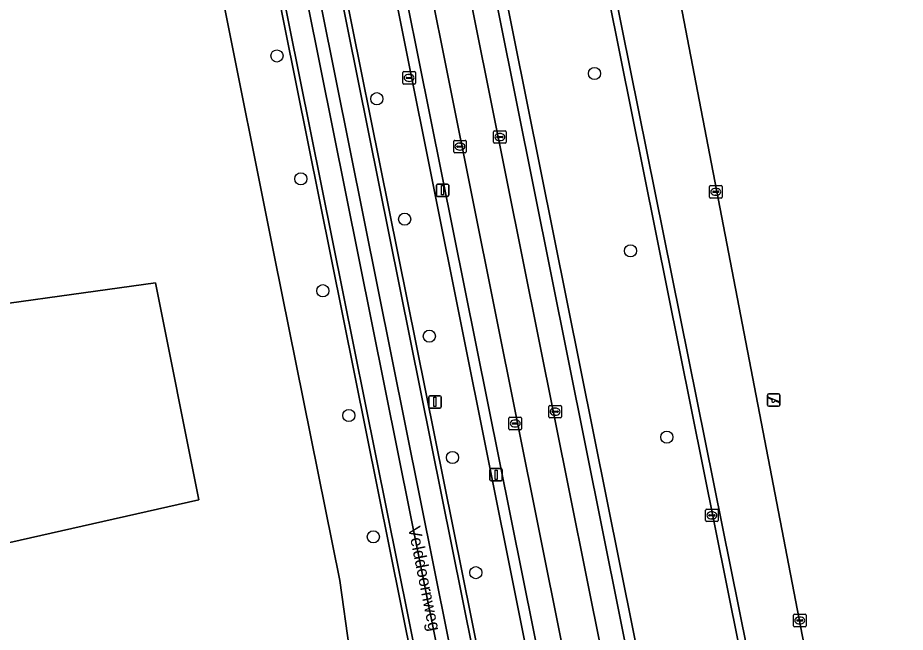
# Model space of a CAD drawing. Extents: x 160203 to 161530, y 379528 to 381797.
# Drawn here: x 160799.8 to 160871, y 380367.4 to 380416.8 of the extents above; entities that cross this region are included whole.
import ezdxf

# ---------------------------------------------------------------- set-up
doc = ezdxf.new("R2010")
doc.units = 0
for name, color, linetype in [('IMGEO_Berm_groen', 7, 'Continuous'), ('IMGEO_Berm_open', 7, 'Continuous'), ('IMGEO_Boom', 7, 'Continuous'), ('IMGEO_Erf', 7, 'Continuous'), ('IMGEO_Grasland_agrarisch', 7, 'Continuous'), ('IMGEO_Groenvoorziening', 7, 'Continuous'), ('IMGEO_Hek', 7, 'Continuous'), ('IMGEO_Kolk', 7, 'Continuous'), ('IMGEO_Lichtmast', 7, 'Continuous'), ('IMGEO_Loofbos', 7, 'Continuous'), ('IMGEO_Openbare_ruimte_label', 7, 'Continuous'), ('IMGEO_Parkeervlak_open', 7, 'Continuous'), ('IMGEO_Rijbaan_lokaal_gesloten', 7, 'Continuous'), ('IMGEO_Rijbaan_lokaal_open', 7, 'Continuous'), ('IMGEO_Rioolput', 7, 'Continuous'), ('IMGEO_Speelvoorziening', 7, 'Continuous'), ('IMGEO_Voetpad_open', 7, 'Continuous'), ('IMGEO_Waterleidingput', 7, 'Continuous')]:
    doc.layers.add(name, color=color, linetype=linetype)

msp = doc.modelspace()

# ---------------------------------------------------------------- linework, layer by layer
at = {"layer": 'IMGEO_Berm_groen'}
for points in [[(160830.916, 380414.289), (160819.918, 380469.339), (160814.915, 380494.379), (160811.026, 380493.513), (160814.089, 380478.303), (160841.379, 380342.789), (160841.726, 380341.019), (160841.352, 380340.899), (160841.381, 380340.684), (160841.823, 380340.142)], [(160845.412, 380338.924), (160846.061, 380339.046), (160841.959, 380359.232), (160830.916, 380414.289)]]:
    msp.add_lwpolyline(points, dxfattribs=at)
at = {"layer": 'IMGEO_Berm_open'}
msp.add_lwpolyline([(160809.488, 380490.62), (160808.357, 380496.254), (160807.806, 380496.157), (160807.391, 380496.064), (160808.139, 380492.044), (160808.457, 380490.462), (160846.915, 380299.112), (160856.862, 380248.916), (160857.878, 380249.092), (160847.878, 380299.47)], close=True, dxfattribs=at)
at = {"layer": 'IMGEO_Boom'}
for centre in [(160820.577, 380413.686), (160846.083, 380412.28), (160828.604, 380410.248), (160822.492, 380403.806), (160830.836, 380400.572), (160848.977, 380398.029), (160824.267, 380394.82), (160832.815, 380391.167), (160826.35, 380384.795), (160851.892, 380383.061), (160834.682, 380381.421), (160828.319, 380375.049), (160836.549, 380372.17)]:
    msp.add_circle(centre, 0.489, dxfattribs=at)
at = {"layer": 'IMGEO_Erf'}
for points in [[(160786.215, 380358.257), (160807.904, 380361.665), (160818.583, 380363.901), (160826.408, 380365.955), (160825.615, 380371.544), (160820.389, 380397.556), (160816.06, 380419.106), (160814.776, 380425.496), (160813.712, 380431.457), (160802.128, 380489.092), (160796.963, 380489.418)], [(160792.299, 380392.893), (160810.816, 380395.452), (160814.313, 380378.028), (160775.372, 380369.231)]]:
    msp.add_lwpolyline(points, dxfattribs=at)
at = {"layer": 'IMGEO_Grasland_agrarisch'}
msp.add_lwpolyline([(160770.881, 380415.989), (160759.176, 380415.089), (160754.769, 380413.373), (160762.756, 380386.034), (160764.96, 380380.474), (160767.455, 380377.256), (160770.696, 380373.902), (160775.372, 380369.231), (160814.313, 380378.028), (160810.816, 380395.452), (160792.299, 380392.893), (160790.929, 380411.368), (160771.323, 380410.232)], close=True, dxfattribs=at)
at = {"layer": 'IMGEO_Groenvoorziening'}
for points in [[(160947.345, 380500), (160946.869, 380502.452), (160944.615, 380512.001), (160902.101, 380503.8), (160879.901, 380499.518), (160834.638, 380490.788), (160834.2, 380490.611), (160833.852, 380490.316), (160833.56, 380489.783), (160833.499, 380489.33), (160863.045, 380342.63), (160874.441, 380344.866), (160898.366, 380349.337), (160907.573, 380354.284), (160962.354, 380365.201), (160969.347, 380366.563), (160972.472, 380371.216), (160971.163, 380377.952), (160966.73, 380400.144), (160956.686, 380451.885)], [(160862.461, 380342.515), (160831.887, 380494.616), (160824.092, 380492.861), (160839.604, 380415.212), (160854.574, 380340.734), (160857.758, 380341.542)], [(160966.11, 380373.245), (160953.284, 380437.896), (160852.978, 380417.957), (160865.398, 380353.411)], [(160953.284, 380437.896), (160966.11, 380373.245), (160865.398, 380353.411), (160852.978, 380417.957)]]:
    msp.add_lwpolyline(points, close=True, dxfattribs=at)
at = {"layer": 'IMGEO_Hek'}
msp.add_lwpolyline([(160831.887, 380494.616), (160862.461, 380342.515)], dxfattribs=at)
at = {"layer": 'IMGEO_Kolk'}
for p, q in [((160837.979, 380406.746), (160837.979, 380407.598)), ((160838.054, 380407.672), (160838.906, 380407.672)), ((160838.467, 380407.452), (160838.492, 380407.452)), ((160838.98, 380407.598), (160838.98, 380406.746)), ((160834.776, 380405.975), (160834.776, 380406.827)), ((160834.851, 380406.901), (160835.703, 380406.901)), ((160835.264, 380406.681), (160835.289, 380406.681)), ((160835.777, 380406.827), (160835.777, 380405.975)), ((160838.906, 380406.672), (160838.054, 380406.672)), ((160838.238, 380407.166), (160838.238, 380407.178)), ((160838.676, 380407.129), (160838.278, 380407.129)), ((160838.281, 380407.215), (160838.679, 380407.215)), ((160838.49, 380406.892), (160838.465, 380406.892)), ((160838.722, 380407.178), (160838.722, 380407.166)), ((160835.035, 380406.395), (160835.035, 380406.407)), ((160835.473, 380406.358), (160835.075, 380406.358)), ((160835.078, 380406.444), (160835.476, 380406.444)), ((160835.287, 380406.121), (160835.262, 380406.121)), ((160835.519, 380406.407), (160835.519, 380406.395)), ((160835.703, 380405.901), (160834.851, 380405.901)), ((160842.418, 380384.677), (160842.418, 380385.529)), ((160842.493, 380385.603), (160843.345, 380385.603)), ((160842.906, 380385.383), (160842.931, 380385.383)), ((160843.419, 380385.529), (160843.419, 380384.677)), ((160839.211, 380383.729), (160839.211, 380384.581)), ((160839.286, 380384.655), (160840.138, 380384.655)), ((160840.212, 380384.581), (160840.212, 380383.729)), ((160843.345, 380384.603), (160842.493, 380384.603)), ((160842.677, 380385.097), (160842.677, 380385.109)), ((160843.115, 380385.06), (160842.717, 380385.06)), ((160842.72, 380385.146), (160843.118, 380385.146)), ((160842.929, 380384.823), (160842.904, 380384.823)), ((160843.161, 380385.109), (160843.161, 380385.097)), ((160839.47, 380384.149), (160839.47, 380384.161)), ((160839.908, 380384.112), (160839.51, 380384.112)), ((160839.513, 380384.198), (160839.911, 380384.198)), ((160839.722, 380383.875), (160839.697, 380383.875)), ((160839.699, 380384.435), (160839.724, 380384.435)), ((160839.954, 380384.161), (160839.954, 380384.149)), ((160840.138, 380383.655), (160839.286, 380383.655))]:
    msp.add_line(p, q, dxfattribs=at)
for points in [[(160837.979, 380406.746), (160837.979, 380407.598)], [(160838.054, 380407.672), (160838.906, 380407.672)], [(160838.98, 380407.598), (160838.98, 380406.746)], [(160834.776, 380405.975), (160834.776, 380406.827)], [(160834.851, 380406.901), (160835.703, 380406.901)], [(160835.777, 380406.827), (160835.777, 380405.975)], [(160838.906, 380406.672), (160838.054, 380406.672)], [(160835.703, 380405.901), (160834.851, 380405.901)], [(160842.418, 380384.677), (160842.418, 380385.529)], [(160842.493, 380385.603), (160843.345, 380385.603)], [(160843.419, 380385.529), (160843.419, 380384.677)], [(160839.211, 380383.729), (160839.211, 380384.581)], [(160839.286, 380384.655), (160840.138, 380384.655)], [(160840.212, 380384.581), (160840.212, 380383.729)], [(160843.345, 380384.603), (160842.493, 380384.603)], [(160840.138, 380383.655), (160839.286, 380383.655)]]:
    msp.add_lwpolyline(points, dxfattribs=at)
for centre, radius, start, end in [((160838.056, 380407.596), 0.0765, 91.55205, 178.44795), ((160838.056, 380407.596), 0.0765, 91.55205, 178.44795), ((160838.904, 380407.596), 0.0765, 1.55205, 88.44795), ((160838.904, 380407.596), 0.0765, 1.55205, 88.44795), ((160834.853, 380406.825), 0.0765, 91.55205, 178.44795), ((160834.853, 380406.825), 0.0765, 91.55205, 178.44795), ((160835.701, 380406.825), 0.0765, 1.55205, 88.44795), ((160835.701, 380406.825), 0.0765, 1.55205, 88.44795), ((160838.056, 380406.748), 0.0765, 181.55205, 268.44795), ((160838.056, 380406.748), 0.0765, 181.55205, 268.44795), ((160838.278, 380407.175), 0.0403, 85.87752, 175.75265), ((160838.275, 380407.165), 0.0366, 178.93798, 274.71019), ((160838.679, 380407.172), 0.043, 264.86636, 352.45326), ((160838.683, 380407.177), 0.0386, 1.73085, 96.63898), ((160838.904, 380406.748), 0.0765, 271.55205, 358.44795), ((160838.904, 380406.748), 0.0765, 271.55205, 358.44795), ((160834.853, 380405.977), 0.0765, 181.55205, 268.44795), ((160834.853, 380405.977), 0.0765, 181.55205, 268.44795), ((160835.075, 380406.404), 0.0403, 85.87752, 175.75265), ((160835.072, 380406.394), 0.0366, 178.93798, 274.71019), ((160835.476, 380406.401), 0.043, 264.86636, 352.45326), ((160835.48, 380406.406), 0.0386, 1.73085, 96.63898), ((160835.701, 380405.977), 0.0765, 271.55205, 358.44795), ((160835.701, 380405.977), 0.0765, 271.55205, 358.44795), ((160842.495, 380385.527), 0.0765, 91.55205, 178.44795), ((160842.495, 380385.527), 0.0765, 91.55205, 178.44795), ((160843.343, 380385.527), 0.0765, 1.55205, 88.44795), ((160843.343, 380385.527), 0.0765, 1.55205, 88.44795), ((160839.288, 380384.579), 0.0765, 91.55205, 178.44795), ((160839.288, 380384.579), 0.0765, 91.55205, 178.44795), ((160840.136, 380384.579), 0.0765, 1.55205, 88.44795), ((160840.136, 380384.579), 0.0765, 1.55205, 88.44795), ((160842.495, 380384.679), 0.0765, 181.55205, 268.44795), ((160842.495, 380384.679), 0.0765, 181.55205, 268.44795), ((160842.717, 380385.106), 0.0403, 85.87752, 175.75265), ((160842.714, 380385.096), 0.0366, 178.93798, 274.71019), ((160843.118, 380385.103), 0.043, 264.86636, 352.45326), ((160843.122, 380385.108), 0.0386, 1.73085, 96.63898), ((160843.343, 380384.679), 0.0765, 271.55205, 358.44795), ((160843.343, 380384.679), 0.0765, 271.55205, 358.44795), ((160839.51, 380384.158), 0.0403, 85.87752, 175.75265), ((160839.507, 380384.148), 0.0366, 178.93798, 274.71019), ((160839.911, 380384.155), 0.043, 264.86636, 352.45326), ((160839.915, 380384.16), 0.0386, 1.73085, 96.63898), ((160839.288, 380383.731), 0.0765, 181.55205, 268.44795), ((160839.288, 380383.731), 0.0765, 181.55205, 268.44795), ((160840.136, 380383.731), 0.0765, 271.55205, 358.44795), ((160840.136, 380383.731), 0.0765, 271.55205, 358.44795)]:
    msp.add_arc(centre, radius, start, end, dxfattribs=at)
for centre, major_axis, ratio, start_param, end_param in [((160838.466, 380407.172), (-0.387, 0.002), 0.722429, 4.712389, 7.853982), ((160838.491, 380407.172), (-0.39, 0.002), 0.717154, 1.570796, 4.712389), ((160835.263, 380406.401), (-0.387, 0.002), 0.722429, 4.712389, 7.853982), ((160835.288, 380406.401), (-0.39, 0.002), 0.717154, 1.570796, 4.712389), ((160842.905, 380385.103), (-0.387, 0.002), 0.722429, 4.712389, 7.853982), ((160842.93, 380385.103), (-0.39, 0.002), 0.717154, 1.570796, 4.712389), ((160839.698, 380384.155), (-0.387, 0.002), 0.722429, 4.712389, 7.853982), ((160839.723, 380384.155), (-0.39, 0.002), 0.717154, 1.570796, 4.712389)]:
    msp.add_ellipse(centre, major_axis=major_axis, ratio=ratio, start_param=start_param, end_param=end_param, dxfattribs=at)
at = {"layer": 'IMGEO_Lichtmast'}
for p, q in [((160833.379, 380402.496), (160833.379, 380403.296)), ((160833.379, 380403.296), (160833.379, 380402.496)), ((160833.479, 380403.396), (160834.269, 380403.396)), ((160834.269, 380403.396), (160833.479, 380403.396)), ((160834.369, 380403.296), (160834.369, 380402.496)), ((160834.369, 380402.496), (160834.369, 380403.296)), ((160834.269, 380402.396), (160833.479, 380402.396)), ((160833.479, 380402.396), (160834.269, 380402.396)), ((160832.765, 380385.483), (160832.765, 380386.283)), ((160832.765, 380386.283), (160832.765, 380385.483)), ((160832.865, 380386.383), (160833.655, 380386.383)), ((160833.655, 380386.383), (160832.865, 380386.383)), ((160833.755, 380386.283), (160833.755, 380385.483)), ((160833.755, 380385.483), (160833.755, 380386.283)), ((160833.655, 380385.383), (160832.865, 380385.383)), ((160832.865, 380385.383), (160833.655, 380385.383)), ((160837.681, 380379.638), (160837.681, 380380.438)), ((160837.681, 380380.438), (160837.681, 380379.638)), ((160837.781, 380380.538), (160838.571, 380380.538)), ((160838.571, 380380.538), (160837.781, 380380.538)), ((160838.671, 380380.438), (160838.671, 380379.638)), ((160838.671, 380379.638), (160838.671, 380380.438)), ((160838.571, 380379.538), (160837.781, 380379.538)), ((160837.781, 380379.538), (160838.571, 380379.538))]:
    msp.add_line(p, q, dxfattribs=at)
for points in [[(160833.799, 380403.271), (160833.949, 380403.271), (160833.949, 380402.521), (160833.799, 380402.521), (160833.799, 380403.271)], [(160833.185, 380386.258), (160833.335, 380386.258), (160833.335, 380385.508), (160833.185, 380385.508), (160833.185, 380386.258)], [(160838.101, 380380.413), (160838.251, 380380.413), (160838.251, 380379.663), (160838.101, 380379.663), (160838.101, 380380.413)]]:
    msp.add_lwpolyline(points, dxfattribs=at)
for centre, start, end in [((160833.479, 380403.296), 90, 180), ((160833.479, 380403.296), 90, 180), ((160834.269, 380403.296), 0, 90), ((160834.269, 380403.296), 360, 90), ((160833.479, 380402.496), 180, 270), ((160833.479, 380402.496), 180, 270), ((160834.269, 380402.496), 270, 0), ((160834.269, 380402.496), 270, 0), ((160832.865, 380386.283), 90, 180), ((160832.865, 380386.283), 90, 180), ((160833.655, 380386.283), 0, 90), ((160833.655, 380386.283), 360, 90), ((160832.865, 380385.483), 180, 270), ((160832.865, 380385.483), 180, 270), ((160833.655, 380385.483), 270, 0), ((160833.655, 380385.483), 270, 0), ((160837.781, 380380.438), 90, 180), ((160837.781, 380380.438), 90, 180), ((160838.571, 380380.438), 0, 90), ((160838.571, 380380.438), 360, 90), ((160837.781, 380379.638), 180, 270), ((160837.781, 380379.638), 180, 270), ((160838.571, 380379.638), 270, 0), ((160838.571, 380379.638), 270, 0)]:
    msp.add_arc(centre, 0.1, start, end, dxfattribs=at)
at = {"layer": 'IMGEO_Loofbos'}
msp.add_lwpolyline([(160833.499, 380489.33), (160833.56, 380489.783), (160833.852, 380490.316), (160834.2, 380490.611), (160834.638, 380490.788), (160879.901, 380499.518), (160902.101, 380503.8), (160944.615, 380512.001), (160946.869, 380502.452), (160954.812, 380504.084), (160951.934, 380519.13), (160951.518, 380519.182), (160951.456, 380519.19), (160855.926, 380500), (160832.145, 380494.674), (160831.887, 380494.616), (160862.461, 380342.515), (160863.045, 380342.63)], close=True, dxfattribs=at)
msp.add_lwpolyline([(160648.432, 380344.766), (160669.214, 380365.192), (160738.215, 380433.18), (160774.983, 380469.077), (160775.322, 380469.004), (160775.749, 380468.561), (160779.938, 380472.153), (160779.195, 380472.869), (160796.238, 380490.084), (160796.963, 380489.418), (160802.128, 380489.092), (160813.712, 380431.457), (160814.776, 380425.496), (160816.06, 380419.106), (160820.389, 380397.556), (160825.615, 380371.544), (160826.408, 380365.955), (160827.774, 380366.314), (160839.859, 380298.895), (160845.662, 380271.9), (160849.881, 380272.972), (160844.613, 380299.608), (160806.217, 380490.57)], dxfattribs=at)
at = {"layer": 'IMGEO_Parkeervlak_open'}
for points in [[(160812.447, 380511.162), (160815.089, 380497.738), (160815.195, 380496.812), (160815.874, 380493.74), (160815.85, 380493.584), (160816.238, 380491.656), (160846.771, 380339.726)], [(160817.512, 380510.978), (160821.234, 380492.423), (160851.769, 380340.218), (160854.166, 380340.671)], [(160853.643, 380341.04), (160823.223, 380492.728)], [(160846.518, 380339.145), (160848.829, 380339.603), (160818.287, 380491.97)]]:
    msp.add_lwpolyline(points, dxfattribs=at)
at = {"layer": 'IMGEO_Rijbaan_lokaal_gesloten'}
for points in [[(160805.629, 380549.55), (160803.96, 380549.663), (160803.192, 380541.42), (160802.974, 380538.517), (160802.782, 380535.612), (160802.478, 380529.797), (160802.28, 380523.978), (160802.244, 380521.207), (160802.297, 380518.437), (160802.439, 380515.67), (160802.67, 380512.909), (160802.99, 380510.157), (160803.399, 380507.416), (160803.14, 380507.358), (160803.191, 380506.666), (160806.108, 380492.099), (160806.281, 380492.144), (160806.674, 380490.188), (160845.136, 380298.897)], [(160814.424, 380511.244), (160818.287, 380491.97), (160848.829, 380339.603), (160851.769, 380340.218), (160821.234, 380492.423)], [(160846.915, 380299.112), (160808.457, 380490.462), (160808.139, 380492.044), (160807.391, 380496.064), (160805.705, 380504.893), (160805.12, 380508.385)], [(160806.122, 380508.458), (160806.724, 380505.08), (160805.705, 380504.893), (160807.391, 380496.064), (160807.806, 380496.157), (160808.357, 380496.254), (160809.488, 380490.62), (160847.878, 380299.47)], [(160858.995, 380252.491), (160842.958, 380332.843), (160841.703, 380339.085), (160841.381, 380340.684), (160841.352, 380340.899), (160811.161, 380490.877)]]:
    msp.add_lwpolyline(points, dxfattribs=at)
at = {"layer": 'IMGEO_Rijbaan_lokaal_open'}
for points in [[(160811.026, 380493.513), (160810.646, 380493.434), (160810.731, 380493.012), (160811.161, 380490.877), (160841.352, 380340.899), (160841.726, 380341.019), (160841.379, 380342.789), (160814.089, 380478.303)], [(160806.281, 380492.144), (160806.108, 380492.099), (160805.945, 380492.03), (160806.217, 380490.57), (160844.613, 380299.608), (160849.881, 380272.972), (160856.352, 380240.258), (160858.585, 380228.968), (160864.629, 380198.41), (160865.008, 380198.49), (160858.94, 380229.148), (160845.136, 380298.897), (160806.674, 380490.188)]]:
    msp.add_lwpolyline(points, close=True, dxfattribs=at)
at = {"layer": 'IMGEO_Rioolput'}
for p, q in [((160830.768, 380412.424), (160831.62, 380412.424)), ((160830.693, 380411.498), (160830.693, 380412.35)), ((160830.952, 380411.918), (160830.952, 380411.93)), ((160831.39, 380411.881), (160830.992, 380411.881)), ((160830.995, 380411.967), (160831.393, 380411.967)), ((160831.181, 380412.204), (160831.206, 380412.204)), ((160831.436, 380411.93), (160831.436, 380411.918)), ((160831.694, 380412.35), (160831.694, 380411.498)), ((160831.62, 380411.424), (160830.768, 380411.424)), ((160831.204, 380411.644), (160831.179, 380411.644))]:
    msp.add_line(p, q, dxfattribs=at)
for points in [[(160830.768, 380412.424), (160831.62, 380412.424)], [(160830.693, 380411.498), (160830.693, 380412.35)], [(160831.694, 380412.35), (160831.694, 380411.498)], [(160831.62, 380411.424), (160830.768, 380411.424)]]:
    msp.add_lwpolyline(points, dxfattribs=at)
for centre, radius, start, end in [((160830.77, 380412.348), 0.0765, 91.55205, 178.44795), ((160830.77, 380412.348), 0.0765, 91.55205, 178.44795), ((160831.618, 380412.348), 0.0765, 1.55205, 88.44795), ((160831.618, 380412.348), 0.0765, 1.55205, 88.44795), ((160830.992, 380411.927), 0.0403, 85.87752, 175.75265), ((160830.989, 380411.917), 0.0366, 178.93798, 274.71019), ((160831.393, 380411.924), 0.043, 264.86636, 352.45326), ((160831.397, 380411.929), 0.0386, 1.73085, 96.63898), ((160830.77, 380411.5), 0.0765, 181.55205, 268.44795), ((160830.77, 380411.5), 0.0765, 181.55205, 268.44795), ((160831.618, 380411.5), 0.0765, 271.55205, 358.44795), ((160831.618, 380411.5), 0.0765, 271.55205, 358.44795)]:
    msp.add_arc(centre, radius, start, end, dxfattribs=at)
for centre, major_axis, ratio, start_param, end_param in [((160831.18, 380411.924), (-0.387, 0.002), 0.722429, 4.712389, 7.853982), ((160831.205, 380411.924), (-0.39, 0.002), 0.717154, 1.570796, 4.712389)]:
    msp.add_ellipse(centre, major_axis=major_axis, ratio=ratio, start_param=start_param, end_param=end_param, dxfattribs=at)
at = {"layer": 'IMGEO_Speelvoorziening'}
for p, q in [((160859.973, 380385.638), (160859.973, 380386.438)), ((160859.973, 380386.438), (160859.973, 380385.638)), ((160860.356, 380386.066), (160860.017, 380386.203)), ((160860.042, 380386.263), (160860.918, 380385.91)), ((160860.073, 380386.538), (160860.863, 380386.538)), ((160860.863, 380386.538), (160860.073, 380386.538)), ((160860.894, 380385.85), (160860.554, 380385.987)), ((160860.963, 380386.438), (160860.963, 380385.638)), ((160860.963, 380385.638), (160860.963, 380386.438)), ((160860.863, 380385.538), (160860.073, 380385.538)), ((160860.073, 380385.538), (160860.863, 380385.538))]:
    msp.add_line(p, q, dxfattribs=at)
for centre, radius, start, end in [((160860.073, 380386.438), 0.1, 90, 180), ((160860.073, 380386.438), 0.1, 90, 180), ((160860.03, 380386.233), 0.0327, 68.07798, 248.07798), ((160860.435, 380385.976), 0.12, 130.99278, 5.16318), ((160860.863, 380386.438), 0.1, 0, 90), ((160860.863, 380386.438), 0.1, 360, 90), ((160860.073, 380385.638), 0.1, 180, 270), ((160860.073, 380385.638), 0.1, 180, 270), ((160860.863, 380385.638), 0.1, 270, 0), ((160860.863, 380385.638), 0.1, 270, 0), ((160860.906, 380385.88), 0.0327, 248.07798, 68.07798)]:
    msp.add_arc(centre, radius, start, end, dxfattribs=at)
at = {"layer": 'IMGEO_Voetpad_open'}
for points in [[(160819.469, 380511.448), (160823.223, 380492.728), (160853.643, 380341.04)], [(160814.915, 380494.379), (160819.918, 380469.339), (160830.916, 380414.289), (160841.959, 380359.232), (160846.061, 380339.046), (160846.518, 380339.145)], [(160854.166, 380340.671), (160854.574, 380340.734), (160839.604, 380415.212), (160824.092, 380492.861)], [(160846.771, 380339.726), (160816.238, 380491.656)]]:
    msp.add_lwpolyline(points, dxfattribs=at)
at = {"layer": 'IMGEO_Waterleidingput'}
for p, q in [((160855.323, 380402.342), (160855.323, 380403.194)), ((160855.398, 380403.268), (160856.25, 380403.268)), ((160856.324, 380403.194), (160856.324, 380402.342)), ((160855.582, 380402.762), (160855.582, 380402.774)), ((160856.02, 380402.725), (160855.622, 380402.725)), ((160855.625, 380402.811), (160856.023, 380402.811)), ((160855.834, 380402.488), (160855.809, 380402.488)), ((160855.811, 380403.048), (160855.836, 380403.048)), ((160856.066, 380402.774), (160856.066, 380402.762)), ((160856.25, 380402.268), (160855.398, 380402.268)), ((160855.008, 380376.347), (160855.008, 380377.199)), ((160855.083, 380377.273), (160855.935, 380377.273)), ((160855.267, 380376.767), (160855.267, 380376.779)), ((160855.705, 380376.73), (160855.307, 380376.73)), ((160855.31, 380376.816), (160855.708, 380376.816)), ((160855.496, 380377.053), (160855.521, 380377.053)), ((160855.751, 380376.779), (160855.751, 380376.767)), ((160856.009, 380377.199), (160856.009, 380376.347)), ((160855.935, 380376.273), (160855.083, 380376.273)), ((160855.519, 380376.493), (160855.494, 380376.493)), ((160862.066, 380367.9), (160862.066, 380368.752)), ((160862.141, 380368.826), (160862.993, 380368.826)), ((160862.325, 380368.32), (160862.325, 380368.332)), ((160862.763, 380368.283), (160862.365, 380368.283)), ((160862.368, 380368.369), (160862.766, 380368.369)), ((160862.554, 380368.606), (160862.579, 380368.606)), ((160862.809, 380368.332), (160862.809, 380368.32)), ((160863.067, 380368.752), (160863.067, 380367.9)), ((160862.993, 380367.826), (160862.141, 380367.826)), ((160862.577, 380368.046), (160862.552, 380368.046))]:
    msp.add_line(p, q, dxfattribs=at)
for points in [[(160855.323, 380402.342), (160855.323, 380403.194)], [(160855.398, 380403.268), (160856.25, 380403.268)], [(160856.324, 380403.194), (160856.324, 380402.342)], [(160856.25, 380402.268), (160855.398, 380402.268)], [(160855.008, 380376.347), (160855.008, 380377.199)], [(160855.083, 380377.273), (160855.935, 380377.273)], [(160856.009, 380377.199), (160856.009, 380376.347)], [(160855.935, 380376.273), (160855.083, 380376.273)], [(160862.066, 380367.9), (160862.066, 380368.752)], [(160862.141, 380368.826), (160862.993, 380368.826)], [(160863.067, 380368.752), (160863.067, 380367.9)], [(160862.993, 380367.826), (160862.141, 380367.826)]]:
    msp.add_lwpolyline(points, dxfattribs=at)
for centre, radius, start, end in [((160855.4, 380403.192), 0.0765, 91.55205, 178.44795), ((160855.4, 380403.192), 0.0765, 91.55205, 178.44795), ((160856.248, 380403.192), 0.0765, 1.55205, 88.44795), ((160856.248, 380403.192), 0.0765, 1.55205, 88.44795), ((160855.622, 380402.771), 0.0403, 85.87752, 175.75265), ((160855.619, 380402.761), 0.0366, 178.93798, 274.71019), ((160856.023, 380402.768), 0.043, 264.86636, 352.45326), ((160856.027, 380402.773), 0.0386, 1.73085, 96.63898), ((160855.4, 380402.344), 0.0765, 181.55205, 268.44795), ((160855.4, 380402.344), 0.0765, 181.55205, 268.44795), ((160856.248, 380402.344), 0.0765, 271.55205, 358.44795), ((160856.248, 380402.344), 0.0765, 271.55205, 358.44795), ((160855.085, 380377.197), 0.0765, 91.55205, 178.44795), ((160855.085, 380377.197), 0.0765, 91.55205, 178.44795), ((160855.307, 380376.776), 0.0403, 85.87752, 175.75265), ((160855.304, 380376.766), 0.0366, 178.93798, 274.71019), ((160855.708, 380376.773), 0.043, 264.86636, 352.45326), ((160855.712, 380376.778), 0.0386, 1.73085, 96.63898), ((160855.933, 380377.197), 0.0765, 1.55205, 88.44795), ((160855.933, 380377.197), 0.0765, 1.55205, 88.44795), ((160855.085, 380376.349), 0.0765, 181.55205, 268.44795), ((160855.085, 380376.349), 0.0765, 181.55205, 268.44795), ((160855.933, 380376.349), 0.0765, 271.55205, 358.44795), ((160855.933, 380376.349), 0.0765, 271.55205, 358.44795), ((160862.143, 380368.75), 0.0765, 91.55205, 178.44795), ((160862.143, 380368.75), 0.0765, 91.55205, 178.44795), ((160862.365, 380368.329), 0.0403, 85.87752, 175.75265), ((160862.362, 380368.319), 0.0366, 178.93798, 274.71019), ((160862.766, 380368.326), 0.043, 264.86636, 352.45326), ((160862.77, 380368.331), 0.0386, 1.73085, 96.63898), ((160862.991, 380368.75), 0.0765, 1.55205, 88.44795), ((160862.991, 380368.75), 0.0765, 1.55205, 88.44795), ((160862.143, 380367.902), 0.0765, 181.55205, 268.44795), ((160862.143, 380367.902), 0.0765, 181.55205, 268.44795), ((160862.991, 380367.902), 0.0765, 271.55205, 358.44795), ((160862.991, 380367.902), 0.0765, 271.55205, 358.44795)]:
    msp.add_arc(centre, radius, start, end, dxfattribs=at)
for centre, major_axis, ratio, start_param, end_param in [((160855.81, 380402.768), (-0.387, 0.002), 0.722429, 4.712389, 7.853982), ((160855.835, 380402.768), (-0.39, 0.002), 0.717154, 1.570796, 4.712389), ((160855.495, 380376.773), (-0.387, 0.002), 0.722429, 4.712389, 7.853982), ((160855.52, 380376.773), (-0.39, 0.002), 0.717154, 1.570796, 4.712389), ((160862.553, 380368.326), (-0.387, 0.002), 0.722429, 4.712389, 7.853982), ((160862.578, 380368.326), (-0.39, 0.002), 0.717154, 1.570796, 4.712389)]:
    msp.add_ellipse(centre, major_axis=major_axis, ratio=ratio, start_param=start_param, end_param=end_param, dxfattribs=at)

# ---------------------------------------------------------------- texts
at = {"layer": 'IMGEO_Openbare_ruimte_label'}
msp.add_text('Velddoornweg', height=1, rotation=281.36614, dxfattribs=at).set_placement((160831.104, 380375.785))

doc.saveas('drawing.dxf')
